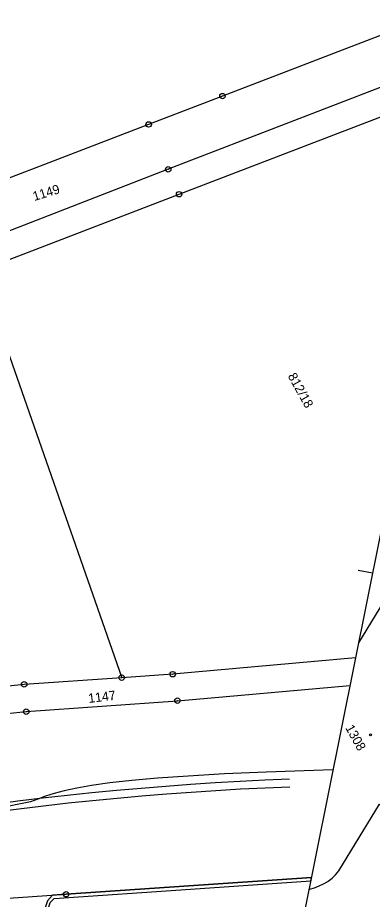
# Model space of a CAD drawing. Extents: x -548552 to -543113, y -1131925 to -1123599.
# Drawn here: x -547972.8 to -547907.6, y -1129760.1 to -1129598 of the extents above; entities that cross this region are included whole.
import ezdxf

# ---------------------------------------------------------------- set-up
doc = ezdxf.new("R2010")
doc.units = 0
for name, color, linetype in [('Hranice parcel', 7, 'Continuous'), ('Parcelní čísla', 7, 'Continuous'), ('Poz předměty', 7, 'Continuous'), ('Profile', 7, 'Continuous'), ('Věcná břemena k části', 7, 'Continuous'), ('Značky bodu BP', 7, 'Continuous'), ('Značky budov', 7, 'Continuous'), ('ŽELEZNICE', 7, 'Continuous')]:
    doc.layers.add(name, color=color, linetype=linetype)

msp = doc.modelspace()

# ---------------------------------------------------------------- linework, layer by layer
at = {"layer": 'Hranice parcel'}
msp.add_line((-547979.82, -1129644.55), (-547953.68, -1129719.36), dxfattribs=at)
for points in [[(-547897.64, -1129598.01), (-547902.31, -1129599.82), (-547935.15, -1129612.43), (-547948.72, -1129617.65), (-547993.15, -1129634.71)], [(-547888.29, -1129603.98), (-547898.68, -1129608), (-547945.12, -1129625.9), (-547988.24, -1129642.57), (-547993.6, -1129646.38), (-547997.26, -1129652.89)], [(-547979.82, -1129644.55), (-547943.11, -1129630.48), (-547896.79, -1129612.71), (-547895.1, -1129612.05)], [(-547905.51, -1129705.42), (-547910.14, -1129712.97)], [(-547910.69, -1129715.69), (-547944.3, -1129718.72), (-547953.68, -1129719.36)], [(-547913.77, -1129754.89), (-547906.27, -1129742.64), (-547904.02, -1129744.01), (-547905.45, -1129746.36), (-547903.68, -1129747.42), (-547904.57, -1129748.87), (-547902.16, -1129750.33), (-547897.62, -1129743.13), (-547900.01, -1129741.62), (-547900.73, -1129742.76), (-547904.88, -1129740.34), (-547889.83, -1129715.74)], [(-547953.68, -1129719.36), (-547971.61, -1129720.59), (-547989.21, -1129722.43), (-547994.01, -1129717.73)], [(-548006.63, -1129729.29), (-547999.25, -1129728.55), (-547971.23, -1129725.6), (-547943.43, -1129723.59), (-547911.71, -1129720.78)], [(-547919.22, -1129758.24), (-547919.12, -1129758.22), (-547918.22, -1129757.98), (-547917.36, -1129757.64), (-547916.54, -1129757.27), (-547915.77, -1129756.81), (-547915.7, -1129756.76), (-547914.99, -1129756.21), (-547914.34, -1129755.58), (-547913.77, -1129754.89)], [(-548012.34, -1129762.51), (-548002.9, -1129761.87), (-547963.89, -1129759.18), (-547918.79, -1129756.09)]]:
    msp.add_lwpolyline(points, dxfattribs=at)
at = {"layer": 'Poz předměty'}
msp.add_line((-547970.42, -1129742.21), (-548030.79, -1129754.35), dxfattribs=at)
msp.add_lwpolyline([(-547914.82, -1129736.33), (-547918.34, -1129736.42), (-547927.1, -1129736.73), (-547934.76, -1129737.06), (-547941.43, -1129737.44), (-547947.06, -1129737.83), (-547951.83, -1129738.25), (-547955.88, -1129738.7), (-547959.2, -1129739.17), (-547961.94, -1129739.65), (-547964.23, -1129740.15), (-547966.11, -1129740.65), (-547967.7, -1129741.17), (-547969.12, -1129741.69), (-547970.42, -1129742.21)], dxfattribs=at)
at = {"layer": 'Profile'}
for p, q in [((-547902.63, -1129675.5), (-547925.74, -1129790.79)), ((-547902.63, -1129675.5), (-547925.74, -1129790.79)), ((-547902.63, -1129675.5), (-547925.74, -1129790.79)), ((-547907.58, -1129700.17), (-547910.16, -1129699.65))]:
    msp.add_line(p, q, dxfattribs=at)
at = {"layer": 'Věcná břemena k části'}
msp.add_line((-547918.92, -1129756.74), (-547918.79, -1129756.09), dxfattribs=at)
msp.add_lwpolyline([(-547918.79, -1129756.09), (-547963.89, -1129759.18), (-547966.39, -1129759.35), (-547967.34, -1129760.4), (-547967.73, -1129761.65), (-547967.75, -1129764.26), (-547967.15, -1129764.27), (-547967.13, -1129761.75), (-547966.81, -1129760.7), (-547966.11, -1129759.93), (-547941.02, -1129758.22), (-547918.92, -1129756.74)], dxfattribs=at)
at = {"layer": 'Značky bodu BP'}
for centre, radius in [((-547935.15, -1129612.43), 0.5), ((-547935.15, -1129612.43), 0.0303), ((-547948.72, -1129617.65), 0.5), ((-547948.72, -1129617.65), 0.0303), ((-547945.12, -1129625.9), 0.5), ((-547945.12, -1129625.9), 0.0303), ((-547943.11, -1129630.48), 0.5), ((-547943.11, -1129630.48), 0.0303), ((-547944.3, -1129718.72), 0.5), ((-547953.68, -1129719.36), 0.5), ((-547953.68, -1129719.36), 0.0303), ((-547944.3, -1129718.72), 0.0303), ((-547971.61, -1129720.59), 0.5), ((-547971.61, -1129720.59), 0.0303), ((-547943.43, -1129723.59), 0.5), ((-547943.43, -1129723.59), 0.0303), ((-547971.23, -1129725.6), 0.5), ((-547971.23, -1129725.6), 0.0303), ((-547963.89, -1129759.18), 0.5), ((-547963.89, -1129759.18), 0.0303)]:
    msp.add_circle(centre, radius, dxfattribs=at)
at = {"layer": 'Značky budov'}
msp.add_circle((-547907.91, -1129729.85), 0.175, dxfattribs=at)
at = {"layer": 'ŽELEZNICE'}
for radius in [585.63, 584.19]:
    msp.add_arc((-547900.33, -1130323.22), radius, 92.19883, 106.46382, dxfattribs=at)

# ---------------------------------------------------------------- texts
at = {"layer": 'Parcelní čísla'}
for s, rotation, p in [('1149', 17.0429, (-547969.74, -1129631.73)), ('812/18', 299.0429, (-547923.19, -1129663.89)), ('1147', 7.0429, (-547959.72, -1129724.02)), ('1308', 299.0429, (-547912.61, -1129728.57))]:
    msp.add_text(s, height=1.7, rotation=rotation, dxfattribs=at).set_placement(p)

doc.saveas('drawing.dxf')
